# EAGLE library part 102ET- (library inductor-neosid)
FILTER dual helix bandpass filter with tab, type E
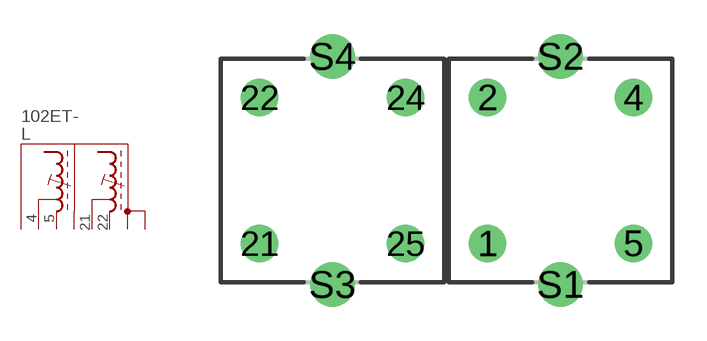
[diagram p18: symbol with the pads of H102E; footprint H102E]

Designator prefix L

## 102ET-452122 (OC_FARNELL: unknown; OC_NEWARK: unknown)  [H102E]
4  IN  pas
5  GND1  pas
21  OUT  pas
22  GND2  pas
S1  S1  pas
S2  S2  pas
S3  S3  pas
S4  S4  pas

## 102ET-422125 (OC_FARNELL: unknown; OC_NEWARK: unknown)  [H102E]
2  GND1  pas
4  IN  pas
21  OUT  pas
25  GND2  pas
S1  S1  pas
S2  S2  pas
S3  S3  pas
S4  S4  pas

## 102ET-512224 (OC_FARNELL: unknown; OC_NEWARK: unknown)  [H102E]
1  GND1  pas
5  IN  pas
22  OUT  pas
24  GND2  pas
S1  S1  pas
S2  S2  pas
S3  S3  pas
S4  S4  pas

## Footprint H102E (pad centres in mm)
DUAL RF COIL ASSEMBLY 10.1, 4 pads, grid 2.5, 10 x 10 x 15 mm
drill 1.1 round: 1 1.8,-3.2; 2 1.8,3.2; 4 8.2,3.2; 5 8.2,-3.2; 21 -8.2,-3.2; 22 -8.2,3.2; 24 -1.8,3.2; 25 -1.8,-3.2
drill 1.3 round: S1 5,-5; S2 5,5; S3 -5,-5; S4 -5,5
